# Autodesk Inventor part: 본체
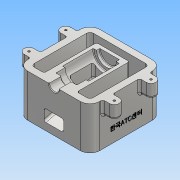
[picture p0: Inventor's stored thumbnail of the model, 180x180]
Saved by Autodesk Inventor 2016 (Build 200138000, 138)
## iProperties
Created: 2018-01
Part Number: 본체
Material: 알루미늄 6061
Document SubType Name: Modeling
Designer: Administrator
Density: 2.7 g/cm^3
Appearance: 알루미늄 - 평지
Mass: 994.989 g
Surface Area: 834.866 cm^2
Volume: 368.514 cm^3
Author: Administrator
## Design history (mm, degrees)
sketch "스케치1"
  geometry: L1 (-55, -55)-(55, -55); L2 (55, -55)-(55, 55); L3 (55, 55)-(-55, 55); L4 (-55, 55)-(-55, -55); L5 (-55, -55)-(55, 55); L6 (55, -55)-(-55, 55); 1 further point
  constraints: 12 end point, 2 midpoint, 2 parallel, 1 horizontal, 1 perpendicular
  dimensions: "d0" = 110 distance of L1.start L1.end; "d1" = 110 distance of L1.end L2.end
extrude "돌출1" new body sketch "스케치1" distance "d2" = 65; taper "d3" = 0 deg
fillet "모깎기1" dims "d4" = 15
feature "쉘1" dims "d5" = 10
sketch "스케치2"
  geometry: L1 (-40, -55)-(40, -55) reference; L2 (-55, 40)-(-55, -40) reference; L3 (-55, -35.5)-(-65, -35.5); L4 (-65, -35.5)-(-65, -20.5); L5 (-65, -20.5)-(-55, -20.5); L6 (-55, -20.5)-(-55, -35.5); A1 r 7.5 centre (-65, -28) between (-65, -20.5) and (-65, -35.5); 1 further point
  constraints: 8 end point, 2 parallel, 2 point on circle, 1 centre point, 1 horizontal, 1 midpoint, 1 perpendicular, 1 point on line
  dimensions: "d6" = 27 distance from line of L1 A1.centre; "d7" = 10 distance of L3.start L3.end; "d8" = 7.5 radius of A1
extrude "돌출2" join sketch "스케치2" distance "d9" = 20; taper "d10" = 0 deg
sketch "스케치4"
  geometry: L1 (-40, 65)-(40, 65) reference; L2 (35, 65)-(35, 30); L3 (35, 30)-(-45, 8.564); L4 (-45, 0)-(-45, 65) reference; L5 (55, 65)-(55, 0) reference; L6 (40, 0)-(-40, 0) reference; L7 (-45, 65)-(35, 65); L8 (-40, 65)-(-40, 0) reference; 1 further point
  constraints: 6 end point, 2 point on line, 1 perpendicular, 1 vertical
  dimensions: "d13" = 20 distance between parallel lines of L5 L2; "d14" = 105 deg angle of L4 L3; "d15" = 30 distance from line of L6 L2.end
extrude "돌출3" join sketch "스케치4" stored distance "d16" = 50; taper "d17" = 0 deg
sketch "스케치6"
  geometry: L1 (-55, 65)-(-40, 65) reference; L2 (40, 65)-(55, 65) reference; L3 (-55, 65)-(30, 65); L4 (-55, 72.5)-(-36, 72.5); L5 (-36, 72.5)-(-36, 81); L6 (-36, 81)-(-22, 81); L7 (-22, 81)-(-22, 85); L8 (-22, 85)-(25, 85); L9 (25, 85)-(25, 80); L10 (25, 80)-(30, 80); L11 (30, 80)-(30, 65); L12 (-55, 0)-(-55, 65) reference; L13 (-55, 72.5)-(-55, 65); 1 further point
  constraints: 20 end point, 7 perpendicular, 2 horizontal, 1 vertical
  dimensions: "d20" = 15 diameter of L4 L3; "d21" = 32 diameter of L6 L3; "d22" = 40 diameter of L8 L3; "d24" = 30 diameter of L10 L3; "d25" = 19 distance of L4.start L4.end; "d26" = 14 distance of L5.end L6.end; "d27" = 47 distance of L7.end L8.end; "d28" = 5 distance of L9.end L10.end
revolve "회전1" sketch "스케치6" stored, may be unused: angle "d29" = 90 deg
sketch "스케치9"
  geometry: L1 (20, 65)-(20, 31.157); L2 (35, 65)-(35, 30); L3 (35, 30)-(-45, 8.564); L4 (-45, 65)-(35, 65); L5 (-55, 11.061)-(20, 31.157); L6 (-55, 0)-(-55, 65) reference; L7 (-55, 29.061)-(-17, 39.243); L8 (-17, 39.243)-(-17, 65); L9 (20.5, 65)-(-20.5, 65) reference; L10 (-17, 65)-(20, 65); L11 (-55, 29.061)-(-55, 11.061); L12 (-22, 65)-(-22, 49) reference; 1 further point
  constraints: 12 end point, 3 point on line, 2 vertical, 1 collinear, 1 horizontal, 1 parallel
  dimensions: "d37" = 5 distance between parallel lines of L3 L5; "d38" = 18 distance of L5.start L7.start; "d39" = 37 distance between parallel lines of L1 L8; "d71" = 5 distance between parallel lines of L12 L8
extrude "돌출4" cut sketch "스케치9" stored distance "d40" = 30; taper "d41" = 0 deg
hole "구멍1" diameter "d44" = 3.242; stored, may be unused: countersink angle "d48" = 90 deg, drill point angle "d50" = 118 deg; dims "d42" = 10, "d43" = 10, "d45" = 9, "d46" = 4, "d47" = 2, "d49" = 11
fillet "모깎기2" dims "d51" = 1
chamfer "모따기2" distance "d52" = 1; stored, may be unused: second distance "d53" = 2, angle "d54" = 45 deg
fillet "모깎기3" dims "d55" = 3
fillet "모깎기4" dims "d56" = 3
fillet "모깎기5" dims "d57" = 3
fillet "모깎기6" dims "d58" = 3
fillet "모깎기7" dims "d59" = 3
fillet "모깎기8" dims "d60" = 3
fillet "모깎기9" dims "d61" = 3
sketch "스케치11"
  geometry: L1 (0, 0)-(0, 80) reference; L2 (-65, -15)-(0, -15) reference; 2 further points
  constraints: 1 other
  dimensions: "d66" = 20 distance from line of L1 point (-20, 40); "d67" = 55 distance from line of L2 point (-20, 40)
feature "엠보싱2" sketch "스케치11" dims "d0" = 110, "d1" = 110, "d6" = 27, "d7" = 10, "d8" = 7.5, "d68" = 0.5, "d69" = 0
node "솔리드1"
mirror "대칭1"
mirror "대칭2"
mirror "대칭3"
mirror "대칭4"
